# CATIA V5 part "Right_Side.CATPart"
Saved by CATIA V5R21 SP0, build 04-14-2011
Part number: Left_Side.1
Bounding box of the stored display mesh (mm): x -172.8 to 2.8, y 0 to 2.8, z -5 to 133.511
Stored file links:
  C:\Users\Pouria\Desktop\Box\Assembled\Right_Side.CATPart
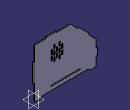
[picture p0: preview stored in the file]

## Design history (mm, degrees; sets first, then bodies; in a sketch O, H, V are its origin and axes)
Body1 (main body)
  Sketch1 on zx-plane, origin (0, 0, 0), H (-1, 0, 0), V (0, 0, 1)
    line L1 (0, 0) -> (0, 40)
    line L2 (0, 130.7107) -> (30, 130.7107)
    point P2 (99.2893, 130.7107)
    line L3 (99.2893, 130.7107) -> (120.5025, 109.4975)
    point P3 (170, 60)
    line L4 (170, 60) -> (170, 40)
    point P4 (170, 0)
    line L5 (147.8, 0) -> (22.2, 0)
    line L6 (45, 12.8) -> (125, 12.8)
    line L7 (125, 12.8) -> (125, 10)
    line L8 (125, 10) -> (45, 10)
    line L9 (45, 10) -> (45, 12.8)
    line L10 (147.8, 0) -> (152.8, -5)
    line L11 (152.8, -5) -> (170, -5)
    point P11 (170, -5)
    line L12 (170, -5) -> (170, 0)
    line L13 (0, 0) -> (0, -5)
    line L14 (0, -5) -> (17.2, -5)
    line L15 (17.2, -5) -> (22.2, 0)
    circle A1 centre (14, 106.7107) radius 1.5
    point P15 (14, 106.7107)
    circle A2 centre (14, 74.7107) radius 1.5
    point P16 (14, 74.7107)
    circle A3 centre (86, 106.7107) radius 1.5
    point P17 (86, 106.7107)
    circle A4 centre (86, 74.7107) radius 1.5
    point P18 (86, 74.7107)
    line L16 (120.5025, 109.4975) -> (122.4824, 111.4774)
    line L17 (122.4824, 111.4774) -> (150.7667, 83.1931)
    line L18 (150.7667, 83.1931) -> (148.7868, 81.2132)
    point P22 (148.7868, 81.2132)
    line L19 (148.7868, 81.2132) -> (170, 60)
    line L20 (30, 130.7107) -> (30, 133.5107)
    line L21 (30, 133.5107) -> (60, 133.5107)
    line L22 (60, 133.5107) -> (60, 130.7107)
    point P26 (60, 130.7107)
    line L23 (170, 40) -> (172.8, 40)
    line L24 (172.8, 40) -> (172.8, 20)
    line L25 (172.8, 20) -> (170, 20)
    point P30 (170, 20)
    line L26 (170, 20) -> (170, 0)
    line L27 (60, 130.7107) -> (99.2893, 130.7107)
    point P31 (0, 90)
    line L28 (0, 90) -> (-2.8, 90)
    line L29 (-2.8, 90) -> (-2.8, 40)
    line L30 (-2.8, 40) -> (0, 40)
    line L31 (0, 90) -> (0, 130.7107)
    length L6 = 80
    distance L8 L6 = 2.8
    distance L7 L4 = 45
    distance L8 L5 = 10
    angle L3 L4 = 135
    angle L10 L5 = 45
    length L12 = 5
    length L11 = 17.2
    length L14 = 17.2
    length L13 = 5
    angle L5 L15 = 45
    distance P4 O = 170
    length L5 = 125.6
    distance P18 P17 H = 0
    distance P16 P15 H = 0
    distance P17 P15 V = 0
    distance P18 P16 V = 0
    distance P18 P16 = 72
    distance P15 P16 = 32
    radius A1 = 1.5
    radius A3 = 1.5
    radius A4 = 1.5
    radius A2 = 1.5
    distance P15 L2 = 24
    distance P15 L1 = 14
    length L17 = 40
    distance L17 L3 = 2.8
    distance L18 P3 = 30
    distance P2 P3 = 100
    length L24 = 20
    length L23 = 2.8
    distance L25 L5 = 20
    distance P3 P4 = 60
    length L21 = 30
    distance L20 L1 = 30
    distance L21 L2 = 2.8
    length L29 = 50
    distance L5 L30 = 40
    distance L29 L1 = 2.8
    vertical: L1 V, L4 V, L7 V, L9 V, L12 V, L13 V, L20 V, L22 V, L24 V, L26 V, L29 V, L31 V
    horizontal: L2 H, L5 H, L6 H, L8 H, L11 H, L14 H, L21 H, L23 H, L25 H, L27 H, L28 H, L30 H
    coincidence: P4 H, P11 L4, L12 L4, L13 L1, P22 L3, L3 L19, P26 L2, P30 L4, L4 L26, L2 L27, P31 L1, L1 L31
    perpendicularity: L18 L3, L16 L3
  Pad1: profile Sketch1, direction (0, 1, 0), length 2.8
  Sketch2 on end face of Pad1, origin (0, 2.8, 0), H (-1, 0, 0), V (0, 0, 1)
    line L1 (77.5, 81.7107) -> (73.5, 81.7107)
    line L2 (73.5, 81.7107) -> (73.5, 69.7107)
    line L3 (73.5, 69.7107) -> (77.5, 69.7107)
    line L4 (77.5, 69.7107) -> (77.5, 81.7107)
    reference projected circle E1 centre (86, 74.7107) radius 1.5 from edge [end face of Pad1 | face of Pad1 from Sketch1.A4]
    reference projected circle E2 centre (86, 74.7107) radius 1.5 from edge [end face of Pad1 | face of Pad1 from Sketch1.A4]
    distance L3 E1 = 3.5
    distance L4 E2 = 10
    length L3 = 4
    length L2 = 12
    horizontal: L1 H, L3 H
    vertical: L2 V, L4 V
  Pocket1: profile Sketch2, direction (0, -1, 0), through (limit type 3)
  RectPattern1: of Pocket1, direction 1 instances 3, spacing 14, along edge [end face of Pad1 | face of Pad1 from Sketch1.L6], direction 2 instances 3, spacing 15, along edge [face of Pad1 from Sketch1.L29 | end face of Pad1] reversed
  Sketch3 on end face of Pad1, origin (0, 2.8, 0), H (-1, 0, 0), V (0, 0, 1)
    line L1 (66.5, 75.7107) -> (70.5, 75.7107)
    line L2 (70.5, 75.7107) -> (70.5, 63.7107)
    line L3 (70.5, 63.7107) -> (66.5, 63.7107)
    line L4 (66.5, 63.7107) -> (66.5, 75.7107)
    reference projected line E1 (73.5, 81.7107) -> (73.5, 69.7107) from edge [end face of Pad1 | face of Pocket1 from Sketch2.L2]
    reference projected line E2 (73.5, 69.7107) -> (77.5, 69.7107) from edge [end face of Pad1 | face of Pocket1 from Sketch2.L3]
    distance L2 E1 = 3
    length L2 = 12
    length L3 = 4
    distance L3 E2 = 6
    horizontal: L1 H, L3 H
    vertical: L2 V, L4 V
  Pocket2: profile Sketch3, direction (0, -1, 0), through (limit type 3)
  RectPattern2: of Pocket2, direction 1 instances 2, spacing 14, along edge [face of Pad1 from Sketch1.L27 | end face of Pad1], direction 2 instances 3, spacing 15, along edge [face of Pad1 from Sketch1.L31 | end face of Pad1] reversed
  Fillet1: radius 1, on edge [face of RectPattern1 | face of RectPattern1] (x32); edge [face of RectPattern2 | face of RectPattern2] (x20); edge [face of Pocket1 from Sketch2.L2 | face of Pocket1 from Sketch2.L1]; edge [face of Pocket2 from Sketch3.L4 | face of Pocket2 from Sketch3.L1]; edge [face of Pocket2 from Sketch3.L3 | face of Pocket2 from Sketch3.L4]; edge [face of Pocket1 from Sketch2.L3 | face of Pocket1 from Sketch2.L2]; edge [face of Pocket1 from Sketch2.L1 | face of Pocket1 from Sketch2.L4]; edge [face of Pocket2 from Sketch3.L1 | face of Pocket2 from Sketch3.L2]; edge [face of Pocket2 from Sketch3.L2 | face of Pocket2 from Sketch3.L3]; edge [face of Pocket1 from Sketch2.L4 | face of Pocket1 from Sketch2.L3]
  Sketch4 on end face of Pad1, origin (0, 2.8, 0), H (-1, 0, 0), V (0, 0, 1)
    line L1 (78.7193, 113.3506) -> (72.6493, 113.3506)
    line L2 (72.6493, 113.3506) -> (72.6493, 98.8904)
    line L3 (72.6493, 98.8904) -> (78.7193, 98.8904)
    line L4 (78.7193, 98.8904) -> (78.7193, 113.3506)
    point P5 (64.9239, 113.3506)
    line L5 (64.9239, 113.3506) -> (58.0813, 113.3506)
    line L6 (58.0813, 113.3506) -> (58.0813, 98.8904)
    line L7 (58.0813, 98.8904) -> (64.9239, 98.8904)
    line L8 (64.9239, 98.8904) -> (64.9239, 113.3506)
    point P7 (58.0813, 98.8904)
    line L9 (50.4662, 112.7031) -> (43.8443, 112.7031)
    line L10 (43.8443, 112.7031) -> (43.8443, 98.8904)
    line L11 (43.8443, 98.8904) -> (50.4662, 98.8904)
    line L12 (50.4662, 98.8904) -> (50.4662, 112.7031)
    point P11 (43.8443, 98.8904)
    horizontal: L1 H, L3 H, L5 H, L7 H, L9 H, L11 H
    vertical: L2 V, L4 V, L6 V, L8 V, L10 V, L12 V
    coincidence: P5 L1, P7 L3, P11 L3
  Pad2: profile Sketch4, direction (0, 1, 0), up to start face of Pad1
  Sketch5 on face of Pad1, origin (0, 2.8, 0), H (-1, 0, 0), V (0, 0, 1)
    line L1 (80.254, 113.5832) -> (93.061, 113.5832)
    line L2 (93.061, 113.5832) -> (93.061, 67.4862)
    line L3 (93.061, 67.4862) -> (80.254, 67.4862)
    line L4 (80.254, 67.4862) -> (80.254, 113.5832)
    point P5 (7.4953, 113.5832)
    line L5 (7.4953, 113.5832) -> (20.1167, 113.5832)
    line L6 (20.1167, 113.5832) -> (20.1167, 65.1269)
    line L7 (20.1167, 65.1269) -> (7.4953, 65.1269)
    line L8 (7.4953, 65.1269) -> (7.4953, 113.5832)
    horizontal: L1 H, L3 H, L5 H, L7 H
    vertical: L2 V, L4 V, L6 V, L8 V
    coincidence: P5 L1
  Pad3: profile Sketch5, direction (0, 1, 0), up to face of Pad1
